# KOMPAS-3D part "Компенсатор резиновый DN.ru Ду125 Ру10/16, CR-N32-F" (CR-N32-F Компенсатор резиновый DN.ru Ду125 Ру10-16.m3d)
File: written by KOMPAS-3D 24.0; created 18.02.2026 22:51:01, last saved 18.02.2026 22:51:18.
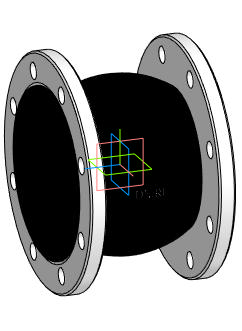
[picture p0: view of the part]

Document properties: Автор: DN.RU; Полное имя файла: D:\PROJECT CAD\DN.RU\...178(2)(ACTUALE). CR-N32-F Компенсатор резиновый DN.ru Ру10-16\CR-N32-F Компенсатор резиновый DN.ru Ру10-16\DN125\CR-N32-F Компенсатор резиновый DN.ru Ду125 Ру10-16 (3d).m3d

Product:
- Body: Твердое тело2  | qty 1
    Масса: 21.558711
- Part/product: Компенсатор резиновый DN.ru Ду125 Ру10/16  | designation CR-N32-F
    Масса: 12
    Раздел спецификации: Прочие изделия
    Комментарий: D140-02395
    Примечание: D140-02380
    additional columns: Типовые

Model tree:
1. Твердое тело2  (labels: Твердое тело2)

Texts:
  CR-N32-F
